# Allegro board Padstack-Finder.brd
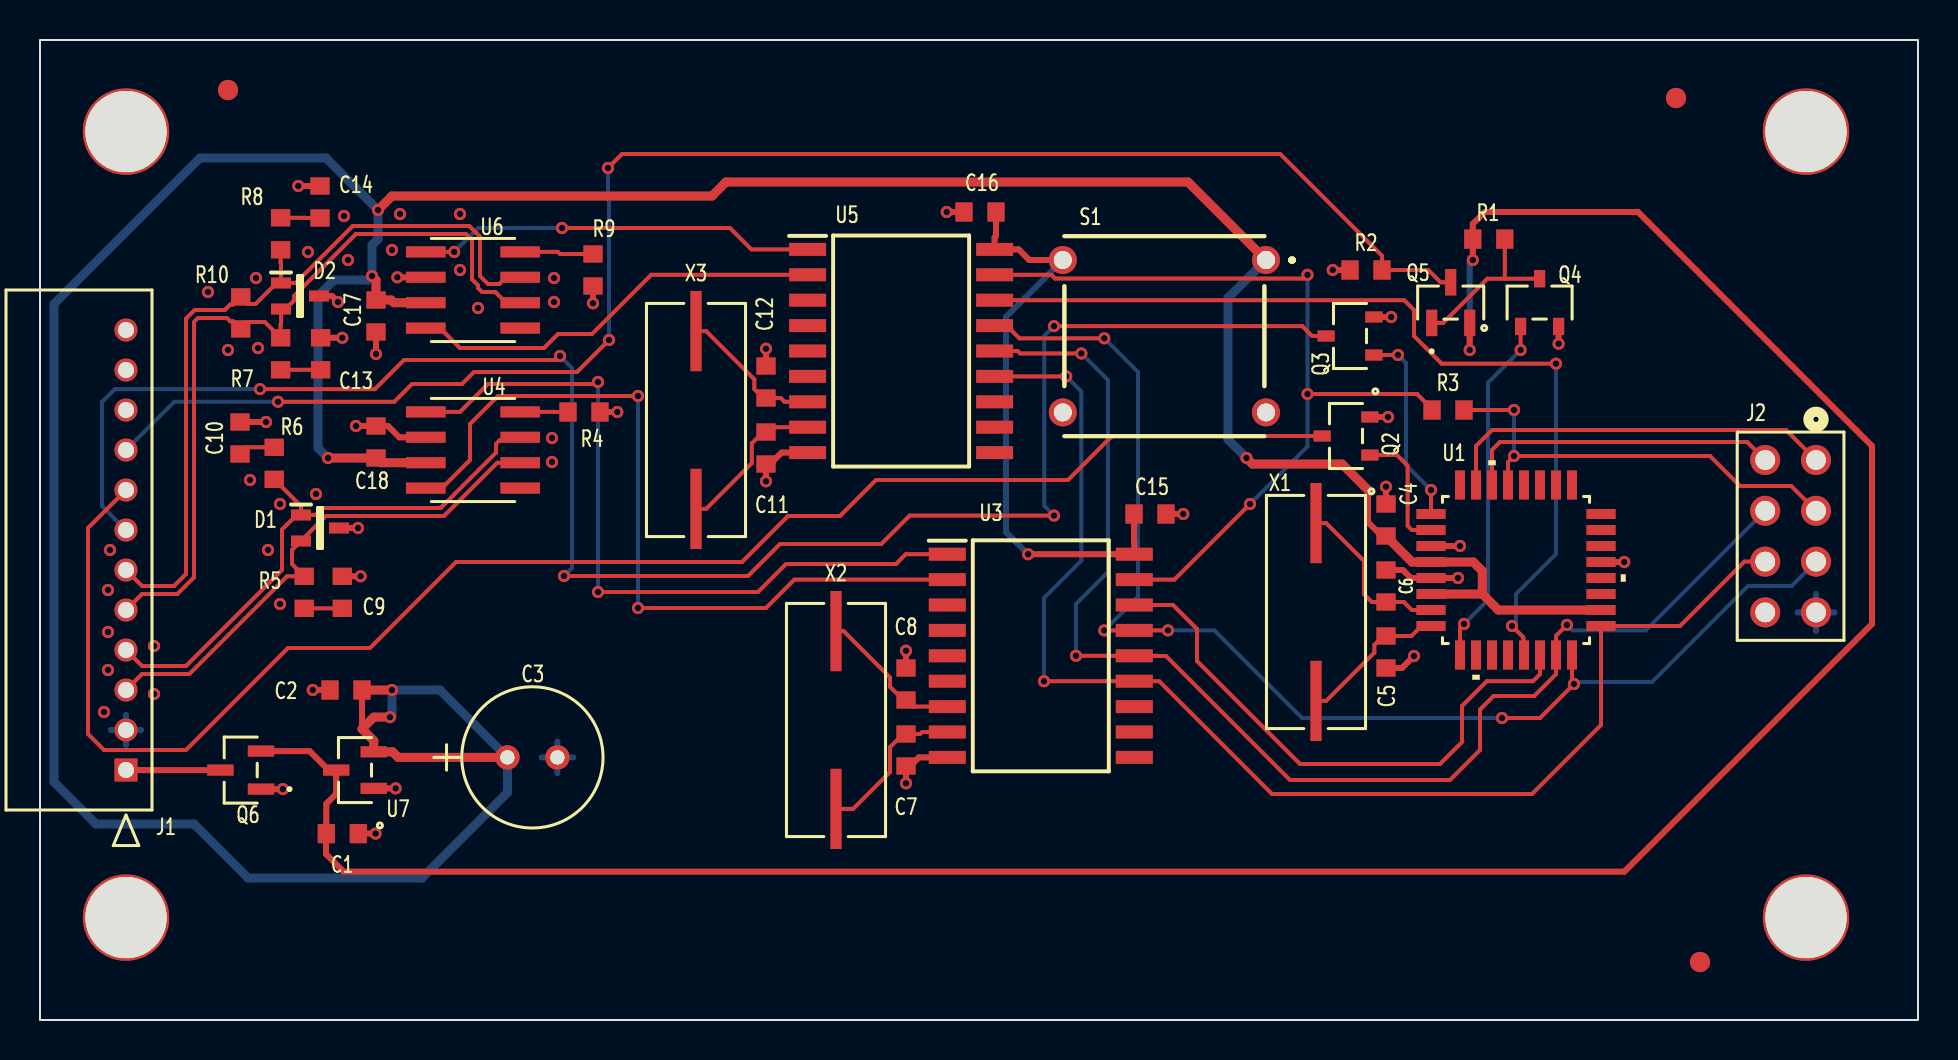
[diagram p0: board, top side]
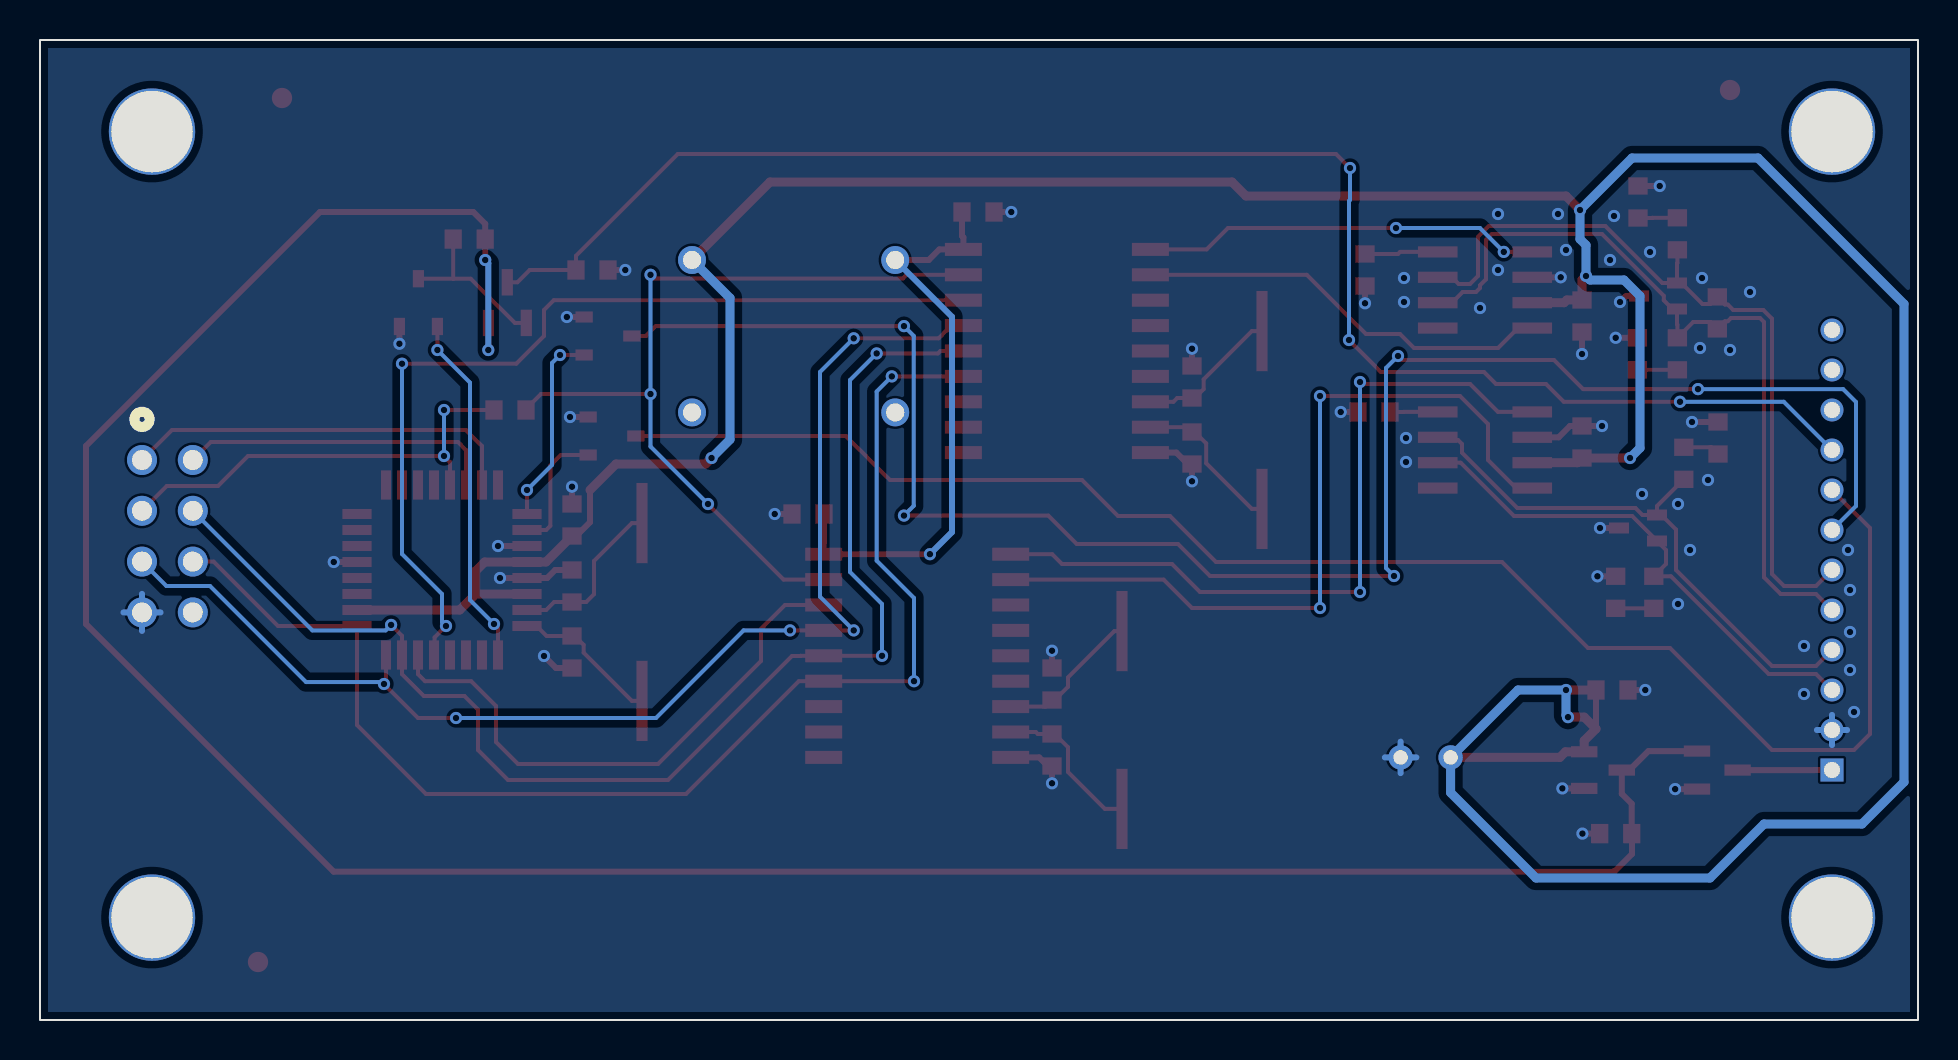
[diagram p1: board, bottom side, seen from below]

Outline 93.9 x 49 mm; copper layers: TOP, BOTTOM. Coordinates in mm from the lower left corner of the outline.
Outline path: rectangle 0,0 93.9,49

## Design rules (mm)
constraint set DEFAULT: 
net group CAR_CAN_DP: nets CAR_CAN_H CAR_CAN_L
net group UNIT_CAN_DP: nets UNIT_CAN_H UNIT_CAN_L

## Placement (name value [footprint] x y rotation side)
C1  0.1u  [0603_AVX]  15.12 9.32 180 top
C2  0.1u  [0603_AVX]  15.3 16.5 0 top
C3  47u  [CAP_MH5_6P3X5_RUB]  23.37 13.13 0 top
C4  0.1u  [0603_AVX]  67.3 25 270 top
C5  22p  [0603_AVX]  67.3 18.4 90 top
C6  22p  [0603_AVX]  67.3 21.7 270 top
C7  22p  [0603_AVX]  43.3 13.5 90 top
C8  22p  [0603_AVX]  43.3 16.8 270 top
C9  560p  [0603_AVX]  15.12 21.38 270 top
C10  560p  [0603_AVX]  10 29.1 270 top
C11  22p  [0603_AVX]  36.3 28.6 90 top
C12  22p  [0603_AVX]  36.3 31.9 270 top
C13  560p  [0603_AVX]  14.03 33.31 270 top
C14  560p  [0603_AVX]  14 40.9 270 top
C15  0.1u  [0603_AVX]  55.5 25.3 180 top
C16  0.1u  [0603_AVX]  47 40.4 0 top
C17  0.1u  [0603_AVX]  16.8 35.2 90 top
C18  0.1u  [0603_AVX]  16.8 28.9 270 top
D1  PESD1CAN-UX  [SOT65P210X110-3N]  14 24.6 0 top
D2  PESD1CAN-UX  [SOT65P210X110-3N]  13 36.2 0 top
J1  12 HEADER  [CON_532541270_MOL]  4.3 12.5 270 top
J2  8 HEADER  [CONN_90131-0764_MOL]  88.8 28 270 top
NOREF  -  [unnamed]  88.3 44.42 0 top
NOREF#2  -  [#2]  -155.7 -328.5 0 top
NOREF#3  -  [unnamed]  4.3 44.42 0 top
NOREF#4  -  [unnamed]  4.3 5.12 0 top
NOREF#5  -  [unnamed]  9.4 46.5 0 top
NOREF#6  -  [unnamed]  88.3 5.12 0 top
NOREF#7  -  [unnamed]  83 2.9 0 top
NOREF#8  -  [unnamed]  81.8 46.1 0 top
Q2  DMN62D0U-7  [PG-SOT23-3-5_INF_MIN]  65.3 29.2 90 top
Q3  DMN62D0U-7  [PG-SOT23-3-5_INF_MIN]  65.5 34.2 90 top
Q4  DMN62D0U-7  [PG-SOT23-3-5_INF_MIN]  74.98 35.87 0 top
Q5  TP0610K  [SOT-23_TP01]  70.54 35.87 0 top
Q6  TP0610K  [SOT-23_TP01]  10.04 12.5 90 top
R1  10k  [0603_AVX]  72.44 39.05 180 top
R2  10k  [0603_AVX]  66.3 37.5 0 top
R3  10k  [0603_AVX]  70.4 30.5 180 top
R4  4.7k  [0603_AVX]  27.2 30.4 180 top
R5  100  [0603_AVX]  13.21 21.38 90 top
R6  100  [0603_AVX]  11.71 27.83 270 top
R7  100  [0603_AVX]  12.03 33.31 90 top
R8  100  [0603_AVX]  12.03 39.31 270 top
R9  4.7k  [0603_AVX]  27.65 37.5 90 top
R10  100  [0603_AVX]  10.04 35.36 270 top
S1  -  [5GTH935NCNO]  61.3 38 0 top
U1  ATMEGA328P-ANR  [32A_ATM]  73.8 22.5 0 top
U3  MCP2515-E_SO  [SOIC127P1030X265-18N]  50.04 18.21 0 top
U4  MCP2551-ISN  [SOIC8-N_MC_MCH]  21.65 28.5 0 top
U5  MCP2515-E_SO  [SOIC127P1030X265-18N]  43.06 33.45 0 top
U6  MCP2551-ISN  [SOIC8-N_MC_MCH]  21.65 36.5 0 top
U7  ZXTR2105F-7  [SOT23_DIO]  15.75 12.5 90 top
X1  SXTHM212EA164-16.000MT  [ABLS-8P000MHZ-B2-T_ABR-L]  63.8 20.4 270 top
X2  SXTHM212EA164-16.000MT  [ABLS-8P000MHZ-B2-T_ABR-L]  39.8 15 90 top
X3  SXTHM212EA164-16.000MT  [ABLS-8P000MHZ-B2-T_ABR-L]  32.8 30 90 top

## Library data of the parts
C1 C2 = C: room: POWER
C3 = C_elect_1: room: POWER
C4 C5 = C: room: PROCESSING
C6 = C: User Part Number: PN; room: PROCESSING
C7-C18 = C: room: TRANSCEIVER
D1 D2 = PESD1CAN-UX_0: room: TRANSCEIVER
J1 = 12 HEADER: room: POWER
J2 = 8 HEADER: room: PROGRAMMING
Q2-Q4 = 2N7002H6327XTSA2_0: room: PROCESSING
Q5 = TP0610K-T1-E3_1: room: PROCESSING
Q6 = TP0610K-T1-E3_1: room: POWER
R1-R3 = R: room: PROCESSING
R4-R10 = R: room: TRANSCEIVER
S1 = 5GTH935NCNO_0: room: PROGRAMMING
U1 = ATMEGA328P-ANR_6: room: PROCESSING
U3 U5 = MCP2515-E_SO_0: room: TRANSCEIVER
U4 U6 = MCP2551-ISN_0: room: TRANSCEIVER
U7 = ZXTR2105F-7_1: room: POWER
X1 = SXTHM212EA164-16_1.000MT: room: PROCESSING
X2 X3 = SXTHM212EA164-16_1.000MT: room: TRANSCEIVER

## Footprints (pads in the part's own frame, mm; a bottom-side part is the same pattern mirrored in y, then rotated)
5GTH935NCNO
  round 1.4 hole 0.9: 1(0,0) 2(-10.16,0) 3(0,-7.62) 4(-10.16,-7.62)
32A_ATM
  rect 1.461x0.501 smd: 1(-4.25,2.8) 2(-4.25,2) 3(-4.25,1.2) 4(-4.25,0.4) 5(-4.25,-0.4) 6(-4.25,-1.2) 7(-4.25,-2) 8(-4.25,-2.8) 17(4.25,-2.8) 18(4.25,-2) 19(4.25,-1.2) 20(4.25,-0.4) 21(4.25,0.4) 22(4.25,1.2) 23(4.25,2) 24(4.25,2.8)
  rect 0.501x1.461 smd: 9(-2.8,-4.25) 10(-2,-4.25) 11(-1.2,-4.25) 12(-0.4,-4.25) 13(0.4,-4.25) 14(1.2,-4.25) 15(2,-4.25) 16(2.8,-4.25) 25(2.8,4.25) 26(2,4.25) 27(1.2,4.25) 28(0.4,4.25) 29(-0.4,4.25) 30(-1.2,4.25) 31(-2,4.25) 32(-2.8,4.25)
0603_AVX
  rect 0.864x0.965 smd: 1(-0.8,0) 2(0.8,0)
ABLS-8P000MHZ-B2-T_ABR-L
  rect 4.013x0.559 smd: 1(-4.445,0) 2(4.445,0)
CAP_MH5_6P3X5_RUB
  round 1.219 hole 0.711: 1(0,0) 2(2.5,0)
CON_532541270_MOL
  rect 1.15x1.15 hole 0.8: 1(0,0)
  round 1.15 hole 0.8: 2(-2,0) 3(-4,0) 4(-6,0) 5(-8,0) 6(-10,0) 7(-12,0) 8(-14,0) 9(-16,0) 10(-18,0) 11(-20,0) 12(-22,0)
CONN_90131-0764_MOL
  round 1.499 hole 0.991: 1(0,0) 2(0,-2.54) 3(2.54,0) 4(2.54,-2.54) 5(5.08,0) 6(5.08,-2.54) 7(7.62,0) 8(7.62,-2.54)
PG-SOT23-3-5_INF_MIN
  rect 0.559x0.864 smd: 1(-0.95,-1.194) 2(0.95,-1.194) 3(0,1.194)
SOIC8-N_MC_MCH
  rect 1.981x0.559 smd: 1(-2.362,1.905) 2(-2.362,0.635) 3(-2.362,-0.635) 4(-2.362,-1.905) 5(2.362,-1.905) 6(2.362,-0.635) 7(2.362,0.635) 8(2.362,1.905)
SOIC127P1030X265-18N
  rect 1.85x0.65 smd: 1(-4.675,5.08) 2(-4.675,3.81) 3(-4.675,2.54) 4(-4.675,1.27) 5(-4.675,0) 6(-4.675,-1.27) 7(-4.675,-2.54) 8(-4.675,-3.81) 9(-4.675,-5.08) 10(4.675,-5.08) 11(4.675,-3.81) 12(4.675,-2.54) 13(4.675,-1.27) 14(4.675,0) 15(4.675,1.27) 16(4.675,2.54) 17(4.675,3.81) 18(4.675,5.08)
SOT23_DIO
  rect 0.559x1.321 smd: 1(-0.915,-0.94) 2(0.915,-0.94) 3(0,0.94)
SOT65P210X110-3N
  rect 1x0.55 smd: 1(-0.95,0.65) 2(-0.95,-0.65) 3(0.95,0)
SOT-23_TP01
  rect 0.559x1.321 smd: 1(-0.95,-1.016) 2(0.95,-1.016) 3(0,1.016)
unnamed
  round 4.318 hole 4.064 unplated: (0,0)

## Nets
+5V: C2.2 C3.1 C4.2 C17.2 C18.2 S1.1 U1.4 U1.6(VCC_1) U1.18 U4.3 U6.3 U7.2(VOUT)
+VIN: C1.2 Q5.2(S) Q6.2(S) R1.2 U7.3
0: C1.1 C2.1 C3.2(-) C4.1 C5.1 C6.1 C7.1 C8.1 C9.1 C10.1 C11.1 C12.1 C13.1 C14.1 C15.1 C16.1 C17.1 C18.1 D1.3(COMMON_CATHODE) D2.3(COMMON_CATHODE) J1.2 J2.7 Q2.2 Q3.2 Q4.2 Q6.1 R2.1 R4.1 R9.1 U1.3 U1.5 U1.21 U3.9(VSS) U4.2(VSS) U5.9(VSS) U6.2(VSS) U7.1
2515_PWR: C15.2 C16.2 S1.2 U3.18 U5.18
+BAT: J1.1 Q6.3
ATMEGA_OSC1: C6.2 U1.7 X1.1
ATMEGA_OSC2: C5.2 U1.8 X1.2(X2)
CAR_CAN_H: D1.1 J1.4 R6.2 U4.7
CAR_CAN_L: D1.2 J1.3 R5.2 U4.6
CAR_CAN_RX: U3.2 U4.4
CAR_CAN_TX: U3.1 U4.1
CAR_CS: U1.14 U3.16
CAR_OSC1: C7.2 U3.8 X2.1
CAR_OSC2: C8.2 U3.7 X2.2(X2)
CAR_RS: R4.2 U4.8
IGNITION_GATE: Q4.1 U1.9
IGNITION_ON: J1.9 Q5.3 R2.2
IGNITION_P_GATE: Q4.3 Q5.1 R1.1
LOCK_GATE: Q3.1 U1.1
LOCK_WIRE: J1.7 Q3.3
MISO: J2.5 U1.16 U3.15 U5.15
MOSI: J2.4 U1.15 U3.14 U5.14
POST_RES_RESET: R3.2 U3.17 U5.17
RESET: J2.3 R3.1 U1.29
RXD: J2.2 U1.30
SCK: J2.6 U1.17 U3.13 U5.13
TXD: J2.1 U1.31
UNIT_CAN_H: D2.1 J1.6 R8.2 R10.1 U6.7
UNIT_CAN_L: D2.2 J1.5 R7.2 R10.2 U6.6
UNIT_CAN_RX: U5.2 U6.4
UNIT_CAN_TX: U5.1 U6.1
UNIT_CS: U1.13 U5.16
UNIT_OSC1: C11.2 U5.8 X3.1
UNIT_OSC2: C12.2 U5.7 X3.2(X2)
UNIT_RS: R9.2 U6.8
UNLOCK_GATE: Q2.1 U1.2
UNLOCK_WIRE: J1.8 Q2.3
N11183: C9.2 R5.1
N11215: C10.2 R6.1
N13031: C13.2 R7.1
N13035: C14.2 R8.1

Pads without a net: J1 10 11 12; J2 8; S1 3 4; U1 10 11 12 19 20 22 23 24 25 26 27 28 32; U3 3 4 5 6 10 11 12; U4 5; U5 3 4 5 6 10 11 12; U6 5

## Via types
v1: diameter 0.61, hole 0.33, TOP to BOTTOM, 102 vias

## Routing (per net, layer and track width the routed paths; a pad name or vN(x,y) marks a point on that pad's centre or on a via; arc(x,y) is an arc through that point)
+5V: length 200.6
  TOP w0.3: 16.1,14.56 C2.2 ; C4.2 67.09,24.2 66.4,24.89 66.4,26.5
  TOP w0.45: U4.3 17.04,27.87 C18.2 v1(14.4,28.1) ; C2.2 v1(17.6,16.5) ; v1(60.32,28.1) 60.62,27.8 65.1,27.8 66.4,26.5 ; S1.1 57.4,41.9 34.3,41.9 33.6,41.2 17.6,41.2 v1(16.9,40.5) ; 72.12,21.3 72.12,22.45 71.67,22.9 U1.4 68.6,22.9 C4.2 ; 72.12,21.3 U1.6 ; 72.12,21.3 72.92,20.5 U1.18 ; v1(16.6,37.2) 16.8,37 C17.2 17.56,36 17.69,35.87 U6.3 ; C3.1 17.91,13.13 17.63,13.41 U7.2 16.69,13.97 16.1,14.56 16.69,15.14 v1(17.5,15.14)
  BOTTOM w0.45: v1(60.32,28.1) 59.4,29.02 59.4,36.1 S1.1 ; v1(17.5,15.14) 17.6,15.24 v1(17.6,16.5) 20,16.5 C3.1 23.37,11.37 19.1,7.1 10.4,7.1 7.7,9.8 2.8,9.8 0.7,11.9 0.7,35.8 8,43.1 14.3,43.1 v1(16.9,40.5) 16.9,39.05 16.6,38.75 v1(16.6,37.2) 16.4,37 14.7,37 13.9,36.2 13.9,28.6 v1(14.4,28.1)
+VIN: length 133
  TOP w0.3: Q6.2 13.48,13.44 14.43,12.5 U7.3 14.81,11.31 14.31,10.81 C1.2 14.3,9.31 14.3,8.3 15.19,7.42 79.22,7.42 91.6,19.8 91.6,28.7 79.9,40.4 72.24,40.4 71.64,39.8 R1.2 v1(71.64,38) ; v1(71.49,33.5) Q5.2
  BOTTOM w0.3: v1(71.64,38) 71.49,37.85 v1(71.49,33.5)
0: length 50.3
  TOP w0.3: v1(36.3,26.94) C11.1 36.51,27.8 37.08,28.37 U5.9 ; Q6.1 v1(12.14,11.55) ; U4.2 17.97,29.13 17.4,29.7 C18.1 v1(15.8,29.7) ; Q2.2 v1(67.4,30.15) ; C9.1 v1(16.03,22.19) ; C1.1 v1(16.78,9.32) ; C6.1 68.14,22.5 68.54,22.1 U1.5 v1(70.9,22.1) ; C5.1 68.1,17.6 v1(68.7,18.2) ; U7.1 v1(17.78,11.58) ; v1(43.3,11.84) C7.1 43.51,12.7 43.94,13.13 U3.9 ; C10.1 v1(11.3,29.9) ; Q4.2 v1(75.93,33.81) ; U1.3 v1(71,23.7) ; C2.1 v1(13.64,16.5) ; R2.1 v1(64.64,37.5) ; D1.3 v1(15.9,24.6) ; C8.1 v1(43.3,18.46) ; D2.3 14.6,36.2 v1(14.9,35.9) ; U1.21 v1(79.21,22.9) ; C16.1 v1(45.34,40.4) ; C15.1 v1(57.16,25.3) ; Q3.2 v1(67.56,35.15) ; R9.1 v1(27.65,35.84) ; C4.1 v1(67.3,26.66) ; U6.2 v1(17.87,37.13) ; C14.1 v1(12.92,41.7) ; C17.1 v1(16.8,33.3) ; C13.1 v1(15.12,34.11) ; C12.1 v1(36.3,33.56) ; R4.1 v1(28.86,30.4)
  BOTTOM w0.3: 25.87,12.34 C3.2 ; C3.2 25.87,13.92 ; C3.2 25.08,13.13 ; C3.2 26.66,13.13 ; J2.7 89.73,20.38 ; J2.7 87.87,20.38 ; J2.7 88.8,19.45 ; J2.7 88.8,21.31 ; 4.3,13.75 J1.2 ; J1.2 5.05,14.5 ; J1.2 3.55,14.5 ; J1.2 4.3,15.25
  vias: v1(3.2,15.4) v1(3.4,21.5) v1(3.4,19.4) v1(3.4,17.5) v1(3.5,23.5) v1(5.7,18.7) v1(5.7,16.3) v1(8.4,36.4) v1(9.4,33.5) v1(10.5,27) v1(10.8,37.1) v1(10.9,33.6) v1(11.4,23.5) v1(12,25.8) v1(12,20.8) v1(13.4,38.4) v1(13.8,26.3) v1(15.2,40.2) v1(15.4,38) v1(17.6,38.5) v1(18,40.3) v1(21,40.3) v1(21,37.5) v1(21.9,35.6) v1(25.6,29.1) v1(25.6,27.9) v1(25.7,37.1) v1(25.7,35.9)
2515_PWR: length 29.2
  TOP w0.3: S1.2 49.46,38 48.93,38.53 U5.18 47.73,39.13 47.8,39.2 C16.2 ; C15.2 54.7,23.91 54.72,23.89 U3.18 v1(49.41,23.29)
  BOTTOM w0.3: v1(49.41,23.29) 48.3,24.39 48.3,35.16 S1.2
+BAT: length 4.7
  TOP w0.3: J1.1 5.15,12.5 5.16,12.5 Q6.3
ATMEGA_OSC1: length 8.5
  TOP w0.2: X1.1 64.31,24.85 66.2,22.95 66.2,21.29 66.59,20.9 C6.2 68.19,20.9 68.59,20.5 U1.7
ATMEGA_OSC2: length 7.5
  TOP w0.2: X1.2 64.31,15.95 66.72,18.37 66.72,18.76 67.16,19.2 C5.2 68.57,19.2 69.07,19.7 U1.8
CAR_CAN_H: length 28.6
  TOP w0.2: D1.1 13.78,25.25 14.13,25.6 20.03,25.6 22.8,28.37 22.8,28.8 23,29 23.88,29 U4.7 ; D1.1 13.05,25.69 R6.2 ; D1.1 12.83,25.25 12.1,24.52 12.1,22.5 7.3,17.7 5.1,17.7 J1.4
CAR_CAN_L: length 26.1
  TOP w0.2: U4.6 22.87,27.87 20.2,25.2 14.29,25.2 13.05,23.96 D1.2 12.6,23.5 12.6,22.8 13.21,22.19 R5.2 12.35,22.19 7.47,17.3 5.1,17.3 J1.3
CAR_CAN_RX: length 40.2
  TOP w0.2: U3.2 37.72,22.02 36.3,20.6 v1(29.9,20.6) ; v1(29.9,31.2) 22.9,31.2 21.5,29.8 21.5,28 20.09,26.6 U4.4
  BOTTOM w0.2: v1(29.9,31.2) v1(29.9,20.6)
CAR_CAN_TX: length 38
  TOP w0.2: v1(27.9,21.4) 35.9,21.4 37.3,22.8 42.8,22.8 43.29,23.29 U3.1 ; U4.1 21,30.4 22.4,31.8 27.8,31.8 v1(27.9,31.9)
  BOTTOM w0.2: v1(27.9,21.4) v1(27.9,31.9)
CAR_CS: length 28.4
  TOP w0.2: U3.16 56.65,20.75 57.85,19.55 57.85,17.95 63,12.8 70,12.8 71.1,13.9 71.1,15.7 72.34,16.94 74.65,16.94 75,17.29 U1.14
CAR_OSC1: length 7.9
  TOP w0.2: U3.8 44.11,14.4 44.01,14.3 C7.2 43.16,14.3 42.5,13.64 42.5,12.4 40.66,10.56 X2.1
CAR_OSC2: length 7.4
  TOP w0.2: U3.7 43.63,15.67 C8.2 43.16,16 42.5,16.66 42.5,17.13 40.18,19.44 X2.2
CAR_RS: length 2.4
  TOP w0.2: R4.2 25.74,30.4 25.74,30.4 U4.8
IGNITION_GATE: length 17.7
  TOP w0.2: U1.9 71,19.6 v1(71.2,19.8) ; Q4.1 v1(74.03,33.5)
  BOTTOM w0.2: v1(71.2,19.8) 72.4,21 72.4,31.87 v1(74.03,33.5)
IGNITION_ON: length 80.5
  TOP w0.2: v1(28.4,42.6) 29.1,43.3 62.01,43.3 67.1,38.21 R2.2 69.41,37.5 70.03,36.89 Q5.3 ; v1(28.45,34) 26.85,32.4 21.7,32.4 21.1,31.8 18.6,31.8 17.71,30.91 v1(11.9,30.91)
  BOTTOM w0.2: v1(11.9,30.91) 6.71,30.91 J1.9 ; v1(28.45,34) 28.45,40.95 28.4,41 v1(28.4,42.6)
IGNITION_P_GATE: length 8.3
  TOP w0.2: 73.24,37.06 72.36,37.06 70.15,34.85 69.59,34.85 ; 73.24,37.06 73.24,37.07 R1.1 ; 73.24,37.06 Q4.3
LOCK_GATE: length 9.8
  TOP w0.2: v1(67.9,33.25) Q3.1 ; U1.1 v1(69.55,26.5)
  BOTTOM w0.2: v1(69.55,26.5) 68.3,27.75 68.3,32.85 v1(67.9,33.25)
LOCK_WIRE: length 91.6
  TOP w0.2: v1(26.2,22.2) 35.4,22.2 37,23.8 42.06,23.8 43.48,25.22 v1(50.7,25.22) ; v1(26,33.2) 25.8,33 18.2,33 16.75,31.55 v1(11,31.55) ; v1(50.7,34.69) 63.11,34.69 63.61,34.2 Q3.3
  BOTTOM w0.2: v1(26.2,22.2) 26.6,22.6 26.6,32.6 v1(26,33.2) ; v1(50.7,25.22) 50.21,25.71 50.21,34.21 v1(50.7,34.69) ; J1.7 3.1,25.7 3.1,30.9 3.75,31.55 v1(11,31.55)
MISO: length 63.9
  TOP w0.2: U5.15 48.33,34.72 48.97,34.08 v1(53.22,34.08) ; U1.16 76.6,16.9 v1(76.7,16.8) 75,15.1 v1(73.1,15.1) ; v1(53.22,19.48) U3.15 v1(56.4,19.48)
  BOTTOM w0.2: v1(56.4,19.48) 58.72,19.48 63.1,15.1 v1(73.1,15.1) ; v1(53.22,34.08) 54.9,32.4 54.9,21.17 v1(53.22,19.48) ; J2.5 87.58,21.7 85.4,21.7 80.6,16.9 76.8,16.9 v1(76.7,16.8)
MOSI: length 65.9
  TOP w0.2: v1(76.35,19.75) 75.8,19.21 U1.15 75.8,17.29 74.71,16.2 72.68,16.2 72,15.52 72,13.5 70.5,12 62.5,12 56.3,18.2 55.88,18.2 55.87,18.21 U3.14 v1(51.8,18.21) ; v1(52.07,33.33) 49,33.33 48.88,33.45 U5.14
  BOTTOM w0.2: J2.4 80.28,19.48 76.62,19.48 v1(76.35,19.75) ; v1(52.07,33.33) 53.4,32 53.4,22.4 51.8,20.8 v1(51.8,18.21)
POST_RES_RESET: length 42.4
  TOP w0.2: v1(63.38,31.3) 68.85,31.3 69.6,30.55 R3.2 ; U3.17 56.72,22.02 v1(60.5,25.8) ; v1(63.38,37.26) 63.19,37.07 50.76,37.07 50.57,37.26 U5.17
  BOTTOM w0.2: v1(60.5,25.8) 63.38,28.68 v1(63.38,31.3) v1(63.38,37.26)
RESET: length 22.6
  TOP w0.2: v1(73.7,30.5) R3.1 ; U1.29 73.4,27.9 v1(73.7,28.2) 83.5,28.2 85,26.7 87.56,26.7 J2.3
  BOTTOM w0.2: v1(73.7,28.2) v1(73.7,30.5)
RXD: length 15.9
  TOP w0.2: U1.30 72.6,28.5 73,28.9 85.36,28.9 J2.2
SCK: length 66
  TOP w0.2: v1(50.2,16.94) U3.13 55.96,16.94 61.6,11.3 74.6,11.3 78.05,14.75 U1.17 82,19.7 85.22,22.92 J2.6 ; U5.13 v1(51.31,32.18)
  BOTTOM w0.2: v1(50.2,16.94) 50.2,21.1 52.07,22.97 52.07,31.42 v1(51.31,32.18)
TXD: length 19.9
  TOP w0.2: U1.31 71.8,28.7 72.6,29.5 87.3,29.5 J2.1
UNIT_CAN_H: length 39.4
  TOP w0.2: U6.7 23.3,37.13 22.97,36.8 22.4,36.8 22,37.2 22,39.17 21.47,39.7 15.63,39.7 12.78,36.85 D2.1 ; D2.1 11.83,36.85 10.78,35.8 10.39,35.8 R10.1 9.65,35.77 9.51,35.77 9.24,35.5 7.73,35.5 7.3,35.07 7.3,22.3 6.7,21.7 5.1,21.7 J1.6 ; D2.1 12.05,37.83 12.03,37.85 R8.2
UNIT_CAN_L: length 39.7
  TOP w0.2: U6.6 23.3,35.87 22.77,36.4 22.1,36.4 21.9,36.6 21.9,36.73 21.6,37.03 21.6,39 21.3,39.3 15.8,39.3 12.71,36.21 12.71,35.99 12.28,35.55 D2.2 12.05,34.79 12.03,34.77 R7.2 11.24,34.9 10.38,34.9 R10.2 9.65,34.94 9.51,34.94 9.35,35.1 7.9,35.1 7.7,34.9 7.7,22.13 6.87,21.3 5.1,21.3 J1.5
UNIT_CAN_RX: length 21
  TOP w0.2: U6.4 20,34.6 20.99,33.6 25.2,33.6 25.9,34.3 27.6,34.3 30.56,37.26 U5.2
UNIT_CAN_TX: length 20
  TOP w0.2: U5.1 35.57,38.53 34.5,39.6 v1(26.1,39.6) ; v1(20.71,38.4) U6.1
  BOTTOM w0.2: v1(26.1,39.6) 21.91,39.6 v1(20.71,38.4)
UNIT_CS: length 45.9
  TOP w0.2: v1(73.6,19.7) 74.17,19.13 74.17,18.28 U1.13 ; U5.16 68.21,35.99 68.7,35.5 68.7,34.2 70.08,32.81 v1(75.8,32.81)
  BOTTOM w0.2: v1(73.6,19.7) 73.8,19.9 73.8,21.3 75.8,23.3 v1(75.8,32.81)
UNIT_OSC1: length 7.9
  TOP w0.2: U5.8 36.54,29.64 C11.2 36.16,29.4 35.59,28.83 35.59,27.84 33.31,25.56 X3.1
UNIT_OSC2: length 7.3
  TOP w0.2: X3.2 33.31,34.44 35.72,32.03 35.72,31.54 36.16,31.1 C12.2 37.04,31.1 37.23,30.91 U5.7
UNIT_RS: length 3.7
  TOP w0.2: U6.8 25.9,38.4 26,38.3 R9.2
UNLOCK_GATE: length 6.4
  TOP w0.2: U1.2 68.59,24.5 68.38,24.71 68.38,27.72 67.85,28.25 Q2.1
UNLOCK_WIRE: length 81.5
  TOP w0.2: Q2.3 53.6,29.2 51.4,27 41.8,27 40,25.2 37.4,25.2 35.1,22.9 20.8,22.9 16.5,18.6 12.4,18.6 7.3,13.5 3.2,13.5 2.4,14.3 2.4,24.6 J1.8
N11183: length 1.9
  TOP w0.2: R5.1 C9.2
N11215: length 1.8
  TOP w0.2: R6.1 10.34,28.64 C10.2
N13031: length 2
  TOP w0.2: R7.1 C13.2
N13035: length 2
  TOP w0.2: R8.1 13.28,40.11 13.29,40.1 C14.2

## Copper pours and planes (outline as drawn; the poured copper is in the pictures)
0 on BOTTOM: 0.4,48.6 93.5,48.6 93.5,0.4 0.4,0.4
